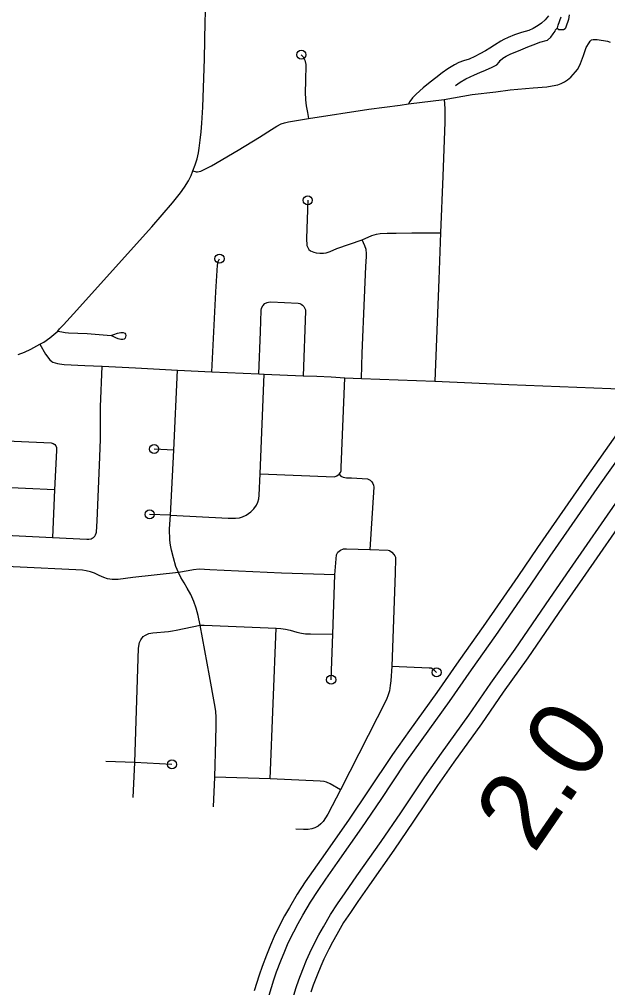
# Model space of a CAD drawing. Extents: x 653372 to 905732, y 627442 to 787275.
# Drawn here: x 669860 to 673100, y 745249 to 750580 of the extents above; entities that cross this region are included whole.
import ezdxf

# ---------------------------------------------------------------- set-up
doc = ezdxf.new("R2010")
doc.units = 0
for name, color, linetype in [('19', 7, 'Continuous'), ('33', 7, 'Continuous'), ('34', 7, 'Continuous'), ('35', 7, 'Continuous'), ('48', 7, 'Continuous')]:
    doc.layers.add(name, color=color, linetype=linetype)

msp = doc.modelspace()

# ---------------------------------------------------------------- linework, layer by layer
at = {"layer": '19'}
for points in [[(673152.3, 748299.1), (672985, 748063.8), (672714.2, 747672.5), (672604.6, 747513.3), (672414.7, 747236.7), (672279.7, 747047.9), (672159.3, 746873.4), (672009.4, 746665.2), (671915.3, 746532), (671781.8, 746332.2), (671676, 746176.2), (671543.4, 745987.1), (671478.3, 745894.6), (671434.5, 745831.2), (671390, 745764), (671348.3, 745690.8), (671320.4, 745643.3), (671295.3, 745593.9), (671263.7, 745529.8), (671243.8, 745482.7), (671220.7, 745427.5), (671197.3, 745365.2), (671180.1, 745317.6), (671154, 745231.2)], [(671235.6, 745207.5), (671260.9, 745290.9), (671277, 745335.8), (671299.7, 745396.1), (671322.2, 745449.8), (671341.1, 745494.5), (671371.3, 745555.9), (671395, 745602.5), (671421.9, 745648.2), (671462.5, 745719.5), (671504.9, 745783.5), (671548, 745846), (671613, 745938.2), (671746, 746128), (671852.3, 746284.7), (671985.4, 746483.8), (672078.6, 746615.9), (672228.8, 746824.5), (672349.3, 746999), (672484.3, 747187.9), (672674.7, 747465.1), (672784.1, 747624.2), (673054.6, 748014.9), (673222, 748250.5)], [(671360.4, 745171.2), (671384.3, 745250), (671399, 745290.9), (671420.6, 745348.1), (671442, 745399.4), (671459.4, 745440.4), (671487.6, 745497.7), (671509.1, 745540), (671534.4, 745583.1), (671573.3, 745651.4), (671612.6, 745710.7), (671654.6, 745771.6), (671719.3, 745863.5), (671853, 746054.2), (671960.1, 746212.1), (672092.5, 746410.2), (672184.4, 746540.4), (672335.1, 746749.6), (672455.6, 746924.3), (672590.8, 747113.3), (672781.8, 747391.5), (672891.1, 747550.4), (673161, 747940.3)], [(673230.6, 747891.5), (672961.1, 747502.1), (672851.9, 747343.3), (672660.4, 747064.5), (672525.2, 746875.4), (672404.5, 746700.6), (672253.6, 746491), (672162.6, 746362.1), (672030.7, 746164.6), (671923, 746005.9), (671788.9, 745814.6), (671724.3, 745723), (671683, 745663.1), (671645.8, 745606.9), (671608, 745540.5), (671583.7, 745499.2), (671563.6, 745459.7), (671536.7, 745405), (671520.4, 745366.5), (671499.6, 745316.7), (671478.8, 745261.5), (671465, 745223.3)]]:
    msp.add_lwpolyline(points, dxfattribs=at)
at = {"layer": '33'}
for points in [[(669852.6, 748734.2), (669889.3, 748748.1), (669923.3, 748763.9), (669973.2, 748791.1), (669995.2, 748803.3), (670027.7, 748827), (670071.4, 748864), (670082, 748876.3), (670103.2, 748899), (670158.8, 748958.3), (670589.6, 749437), (670704, 749569.6), (670747.2, 749624.9), (670770.2, 749656), (670791.6, 749691.6), (670805.8, 749721), (670816.2, 749746.3), (670827.8, 749779.5), (670838.6, 749812.8), (670847.5, 749846.1), (670850.9, 749871.6), (670855.8, 749915.7), (670861.6, 749961.7), (670865.7, 750009.3), (670870.1, 750097.5), (670878.9, 750363.3), (670883.3, 750566.6), (670886.4, 750669.9)], [(672773.4, 750599.3), (672755.5, 750576.9), (672735.8, 750558.4), (672716.4, 750546.2), (672689.1, 750530.5), (672666.5, 750519.1), (672624.8, 750508.2), (672586.8, 750495.3), (672552.7, 750481.1), (672528.7, 750469.1), (672510.9, 750460), (672475.9, 750438.8), (672451.2, 750422.3), (672427.2, 750407.8), (672396.1, 750390.3), (672368.9, 750375.2), (672336.7, 750361.8), (672305.9, 750352.5), (672280.1, 750342.5), (672256.2, 750330.5), (672219.8, 750308), (672187.9, 750285.4), (672152.7, 750258.4), (672122.4, 750235.1), (672083.8, 750202.5), (672045.9, 750169.2), (672025.5, 750147.6), (672009.6, 750128.3), (672004, 750115.4)], [(670816.2, 749746.3), (670833.4, 749740.3), (670841.4, 749740.5), (670859.2, 749745), (670918.2, 749774), (671065.3, 749860.6), (671182.2, 749932.1), (671248.3, 749974), (671278.4, 749992.4), (671301.5, 750004.4), (671319.4, 750011), (671342.6, 750015.6), (671451.5, 750033.6), (671784.4, 750084.9), (671957.4, 750108.4), (672004, 750115.4), (672198.6, 750139.1), (672354.3, 750166.4), (672484.8, 750181.9), (672563.5, 750191.7), (672690.2, 750203.5), (672764.9, 750209.3), (672794.1, 750213.5), (672825.2, 750219.3), (672844.4, 750227.1), (672861.6, 750236.7), (672879.6, 750247.6), (672896.9, 750262.6), (672909.9, 750275.7), (672922.6, 750290.9), (672933.5, 750304.5), (672941.5, 750316.9), (672950.5, 750336.9), (672966.2, 750381.9), (672982.2, 750425), (672997.8, 750451.5), (673004.3, 750460.2), (673011.3, 750466.7), (673020.6, 750469.4), (673041.3, 750469.6), (673098.3, 750459.9), (673114.1, 750454.3)], [(671412.4, 750385.7), (671422.9, 750373.3), (671431.9, 750355.2), (671436.9, 750332.1), (671435.4, 750239.2), (671434.2, 750179.3), (671436.2, 750137.2), (671439.6, 750103.4), (671446.1, 750066.9), (671451.5, 750033.6)], [(672198.6, 750139.1), (672203.6, 750090.2), (672203, 750013.8), (672192.4, 749716.1), (672179, 749405.4), (672169.7, 749147.6), (672147.5, 748587.3)], [(671448.4, 749584.1), (671441.2, 749373.1), (671442.5, 749334.9), (671447.9, 749323.3), (671454.1, 749313.4), (671463.6, 749305.8), (671482, 749297.9), (671494.9, 749295.1), (671514.4, 749292.9), (671534.6, 749292.3), (671549.7, 749295.1), (671571.5, 749301.8), (671608.5, 749317.7), (671748.8, 749367.1), (671801.5, 749389.9), (671826, 749397.3), (671847.5, 749400.4), (671884.9, 749402.5), (671935.4, 749403.7), (672021.5, 749405.2), (672179, 749405.4)], [(671745.1, 748603.4), (671748.8, 748743), (671761.1, 749046.4), (671768.8, 749220.3), (671771.2, 749274.6), (671771.7, 749290.9), (671769.1, 749313.7), (671763.2, 749332.6), (671748.8, 749367.1)], [(670920.8, 748640), (670942.6, 749080), (670949.4, 749198.3), (670951.9, 749227.5), (670955.7, 749246.5), (670962.2, 749262.1)], [(671178.4, 748628.2), (671187.4, 748860.2), (671191.3, 748977.2), (671193.3, 748990.6), (671200.6, 749003.4), (671212.4, 749015.6), (671224.3, 749021.3), (671232.5, 749023.5), (671244.3, 749024), (671395, 749017.8), (671403.9, 749015.9), (671411.9, 749012.8), (671419.4, 749006.9), (671426.1, 748999), (671431.2, 748991.6), (671436.1, 748981.3), (671436.3, 748973.9), (671423.3, 748618)], [(669973.2, 748791.1), (670003.2, 748737.4), (670028.2, 748704.6), (670038.9, 748696.1), (670044.5, 748693.1), (670056.6, 748688.7), (670069.9, 748685.4), (670081.2, 748683.1), (670107.5, 748680.2), (670221.4, 748674.8), (670316.7, 748669.9), (670500.5, 748661.1), (670730.7, 748649), (670920.8, 748640), (671178.4, 748628.2), (671208.1, 748626.5), (671423.3, 748618), (671498.7, 748614.9), (671577.4, 748611.7), (671652.5, 748606.5)], [(669562.2, 747750.9), (670043.1, 747727.5), (670232.5, 747718.1), (670243, 747718.2), (670255.6, 747719.9), (670261.4, 747723), (670268.9, 747727.6), (670274.8, 747734.3), (670279, 747741.1), (670283.8, 747750.7), (670285.2, 747757.2), (670287.8, 747818.4), (670301.5, 748126), (670306.2, 748267.2), (670306.4, 748383), (670307.1, 748446.3), (670316.7, 748669.9)], [(670855.5, 747243.7), (670845.2, 747297.9), (670834.6, 747338.6), (670821.7, 747374.3), (670805.3, 747413), (670785, 747448.2), (670766.8, 747478.1), (670750.1, 747507.3), (670736.5, 747535), (670721.8, 747568.4), (670708.5, 747614.4), (670697.3, 747658.1), (670691.5, 747684.7), (670688.7, 747713.4), (670687.5, 747774.5), (670692, 747849.7), (670710.1, 748208.1), (670730.7, 748649)], [(670692, 747849.7), (671010.4, 747833.5), (671050.8, 747833.8), (671072.2, 747836), (671089.2, 747841.4), (671109.8, 747849.6), (671135.4, 747868), (671152.1, 747885.8), (671165.1, 747905.3), (671173.8, 747922.7), (671179.4, 747940.1), (671181.5, 747959.9), (671186.5, 748077.4), (671208.1, 748626.5)], [(671186.5, 748077.4), (671595, 748060.7), (671609.1, 748066.2), (671621.2, 748076.1), (671628, 748084.7), (671632, 748094.2), (671632.5, 748111.8), (671652.5, 748606.5)], [(671652.5, 748606.5), (671745.1, 748603.4), (672147.5, 748587.3), (672556.3, 748570.1), (673492.2, 748532.9)], [(669585.4, 748268.6), (670036, 748248.2), (670045.9, 748245.3), (670055.7, 748239.2), (670061.3, 748231.6), (670064.7, 748222.6), (670064.8, 748206.2), (670054.5, 747989), (670043.1, 747727.5)], [(670710.1, 748208.1), (670602.3, 748214)], [(671621.2, 748076.1), (671631.1, 748064.8), (671644.2, 748060), (671661.7, 748055.8), (671689.6, 748054.9), (671776.9, 748050.8), (671784.9, 748046.9), (671791.3, 748042.3), (671800.6, 748034), (671807, 748024.2), (671810.4, 748015.3), (671812.3, 748005), (671790, 747661.4)], [(670054.5, 747989), (669573.5, 748010.9)], [(670692, 747849.7), (670577.5, 747854.6)], [(671598.2, 747520.9), (671606.9, 747631.2), (671613.4, 747646.8), (671629.2, 747658.1), (671644.8, 747664.3), (671661.7, 747665.2), (671789.5, 747661.4), (671890.3, 747657.1), (671899, 747655.3), (671911.7, 747646.7), (671923.1, 747633.8), (671928, 747625.6), (671930.7, 747618.2), (671931.9, 747610.8), (671929.5, 747530), (671910.5, 747018.8), (671905.9, 746938.1), (671902.9, 746912.5), (671897.6, 746883.3), (671891.8, 746860.6), (671881.5, 746836), (671627.8, 746338.5), (671558.3, 746203.7), (671533.6, 746164), (671520, 746150.4), (671504.9, 746138.4), (671487.8, 746129.3), (671470.7, 746122.5), (671450, 746120.2), (671425.7, 746118.7), (671383.2, 746120.7)], [(670736.5, 747535), (670485.7, 747506.3), (670403.4, 747496.5), (670370.9, 747495.9), (670345, 747499.1), (670324.9, 747506.2), (670300.1, 747517.5), (670274.5, 747530.5), (670252, 747538.5), (670228.6, 747544), (670207.6, 747547.1), (670171.9, 747549.8), (669556.2, 747578)], [(671598.2, 747520.9), (671304.6, 747530.5), (670908.8, 747549), (670850.9, 747552.2), (670819.9, 747548.7), (670789.6, 747543), (670736.5, 747535)], [(671577.2, 746944.1), (671586.2, 747194.4), (671598.2, 747520.9)], [(670487.3, 746296.2), (670495.2, 746487.8), (670516.3, 747117.3), (670520.9, 747148.7), (670528.7, 747163.9), (670542.5, 747181.9), (670555.2, 747190.3), (670573.1, 747197.9), (670595.3, 747201.6), (670680.7, 747210), (670703.6, 747213), (670724.3, 747216.8), (670855.5, 747243.7)], [(670855.5, 747243.7), (670877.6, 747244.4), (671274.6, 747228), (671299.5, 747226.6), (671325.6, 747221.7), (671350.6, 747216.9), (671388.1, 747205.5), (671413, 747200.4), (671436.4, 747197.5), (671464.3, 747196.6), (671586.2, 747194.4)], [(670928.3, 746243.4), (670936, 746407.5), (670941.5, 746609.7), (670944, 746692), (670943.8, 746735.3), (670942.7, 746771.1), (670934.4, 746813.2), (670907.4, 746965.4), (670855.5, 747243.7)], [(671241.3, 746398.1), (671274.6, 747228)], [(671910.5, 747018.8), (672117.6, 747010.5), (672128.1, 747008.7), (672136.7, 747003.7), (672157.6, 746984.5)], [(670700.6, 746478.1), (670495.2, 746487.8), (670336.7, 746494.2)], [(671627.8, 746338.5), (671572.2, 746370.7), (671551.9, 746380.9), (671538.8, 746383.5), (671516.8, 746386.4), (671241.3, 746398.1), (670936, 746407.5)]]:
    msp.add_lwpolyline(points, dxfattribs=at)
for centre in [(671412.4, 750385.7), (671448.4, 749584.1), (670962.2, 749262.1), (670602.3, 748214), (670577.5, 747854.6), (672157.6, 746984.5), (671577.2, 746944.1), (670700.6, 746478.1)]:
    msp.add_circle(centre, 25, dxfattribs=at)
at = {"layer": '34'}
for points in [[(670071.4, 748864), (670093.7, 748860.1), (670111.8, 748856.7), (670130.9, 748854.3), (670233, 748849.8), (670364.9, 748839.3)], [(670364.9, 748839.3), (670380.5, 748845.4), (670400.3, 748852.3), (670419.6, 748856.4), (670432.6, 748855.5), (670440.5, 748852.5), (670444.5, 748846.8), (670445.7, 748839.2), (670445.5, 748831.8), (670442, 748824.4), (670436.7, 748819), (670429.2, 748817.3), (670418.9, 748818.1), (670404.5, 748821.3), (670390.6, 748825.9), (670364.9, 748839.3)]]:
    msp.add_lwpolyline(points, dxfattribs=at)
at = {"layer": '35'}
for points in [[(672888.3, 750605.7), (672883.4, 750579.5), (672869.9, 750536.9), (672865, 750528.2), (672857.3, 750523.4), (672847.6, 750522.4), (672838.7, 750521.8), (672830.4, 750523.4), (672828.3, 750524.3), (672824.2, 750528.2), (672823.5, 750533.3), (672828.1, 750547.9), (672843.8, 750593.3)], [(672262.7, 750215.4), (672286.8, 750235), (672319.2, 750252.5), (672366.4, 750275.3), (672395.4, 750287.2), (672426.3, 750300.9), (672464.4, 750317), (672489, 750329.6), (672501.5, 750343.9), (672508.1, 750353.2), (672521.9, 750366.2), (672540.7, 750378.4), (672566.8, 750390.9), (672608.7, 750406.8), (672659.7, 750429.5), (672704.1, 750445.4), (672726.7, 750454.2), (672767.8, 750466.4), (672787.4, 750483), (672800, 750501.1), (672810, 750516.1), (672813.4, 750522.3), (672823.5, 750533.3)]]:
    msp.add_lwpolyline(points, dxfattribs=at)

# ---------------------------------------------------------------- texts
at = {"layer": '48'}
msp.add_text('2.0', height=422.4, rotation=55.5533, dxfattribs=at).set_placement((672692.8, 745980.1))

doc.saveas('drawing.dxf')
